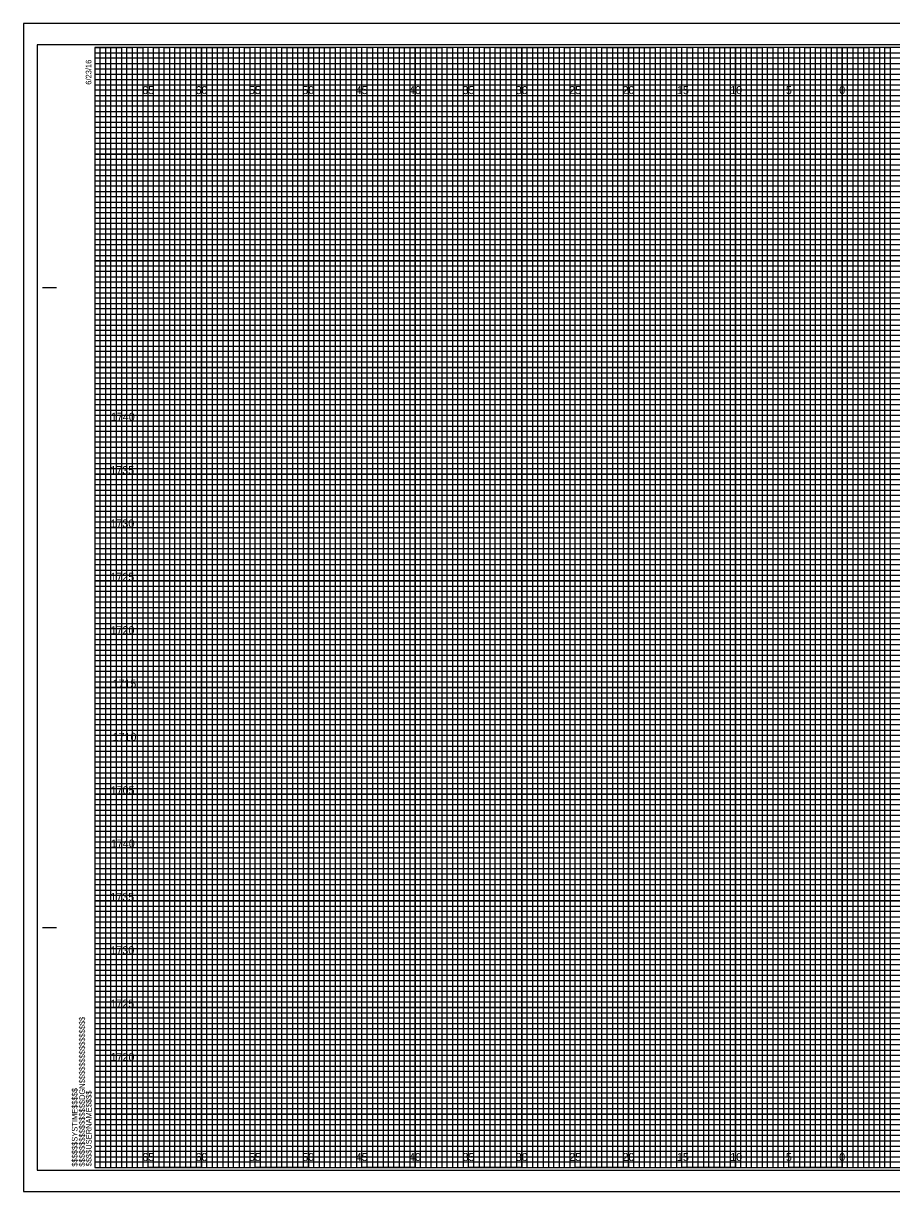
# Model space of a CAD drawing. Extents: x -7 to 162, y -2 to 217.
# Drawn here: x -6.7 to 74.6, y -2.3 to 107.3 of the extents above; entities that cross this region are included whole.
import ezdxf

# ---------------------------------------------------------------- set-up
doc = ezdxf.new("R2010")
doc.units = 0
for name, color, linetype in [('Prop XS Elevation Labels', 7, 'Continuous'), ('Prop XS Offset Labels', 7, 'Continuous'), ('Sheet Cross Section CELL', 7, 'Continuous'), ('Sheet Cross Section Grid Major CELL', 7, 'Continuous'), ('Sheet Cross Section Grid Middle CELL', 7, 'Continuous'), ('Sheet Cross Section Grid Minor 1 CELL', 7, 'Continuous'), ('Sheet Cross Section Grid Minor 2 CELL', 7, 'Continuous'), ('Sheet Cutting Line CELL', 7, 'Continuous'), ('Sheet DOT Grid CELL', 7, 'Continuous'), ('Sheet Plot Border Inside CELL', 7, 'Continuous'), ('Sheet Plot Border Outside CELL', 7, 'Continuous')]:
    doc.layers.add(name, color=color, linetype=linetype)

msp = doc.modelspace()

# ---------------------------------------------------------------- linework, layer by layer
at = {"layer": 'Sheet Cross Section CELL'}
for p, q in [((-4.9, 82.5), (-3.65, 82.5)), ((-4.85, 82.5), (-3.6, 82.5)), ((-4.9, 22.5), (-3.65, 22.5)), ((-4.85, 22.5), (-3.6, 22.5)), ((0, 0), (0, 0)), ((0, 0), (0, 0)), ((0, 0), (0, 0)), ((0, 0), (0, 0)), ((0, 0), (0, 0)), ((0, 0), (0, 0)), ((0, 0), (0, 0))]:
    msp.add_line(p, q, dxfattribs=at)
msp.add_lwpolyline([(160, 105), (0, 105), (0, 0), (160, 0)], close=True, dxfattribs=at)
at = {"layer": 'Sheet Cross Section Grid Major CELL'}
for p, q in [((5, 105), (0, 105)), ((5, 0), (5, 105)), ((15, 105), (10, 105)), ((10, 105), (10, 0)), ((15, 0), (15, 105)), ((25, 105), (20, 105)), ((20, 105), (20, 0)), ((25, 0), (25, 105)), ((35, 105), (30, 105)), ((30, 105), (30, 0)), ((35, 0), (35, 105)), ((45, 105), (40, 105)), ((40, 105), (40, 0)), ((45, 0), (45, 105)), ((55, 105), (50, 105)), ((50, 105), (50, 0)), ((55, 0), (55, 105)), ((65, 105), (60, 105)), ((60, 105), (60, 0)), ((65, 0), (65, 105)), ((75, 105), (70, 105)), ((70, 105), (70, 0)), ((10, 0), (5, 0)), ((20, 0), (15, 0)), ((30, 0), (25, 0)), ((40, 0), (35, 0)), ((50, 0), (45, 0)), ((60, 0), (55, 0)), ((70, 0), (65, 0))]:
    msp.add_line(p, q, dxfattribs=at)
for points in [[(0, 100), (160, 100), (160, 95), (0, 95)], [(0, 90), (160, 90), (160, 85), (0, 85)], [(0, 80), (160, 80), (160, 75), (0, 75)], [(0, 70), (160, 70), (160, 65), (0, 65)], [(0, 60), (160, 60), (160, 55), (0, 55)], [(0, 50), (160, 50), (160, 45), (0, 45)], [(0, 40), (160, 40), (160, 35), (0, 35)], [(0, 30), (160, 30), (160, 25), (0, 25)], [(0, 20), (160, 20), (160, 15), (0, 15)], [(0, 10), (160, 10), (160, 5), (0, 5)]]:
    msp.add_lwpolyline(points, dxfattribs=at)
at = {"layer": 'Sheet Cross Section Grid Middle CELL'}
for points in [[(0, 105), (2.5, 105), (2.5, 0), (7.5, 0), (7.5, 105), (12.5, 105), (12.5, 0), (17.5, 0), (17.5, 105), (22.5, 105), (22.5, 0), (27.5, 0), (27.5, 105), (32.5, 105), (32.5, 0), (37.5, 0), (37.5, 105), (42.5, 105), (42.5, 0), (47.5, 0), (47.5, 105), (52.5, 105), (52.5, 0), (57.5, 0), (57.5, 105), (62.5, 105), (62.5, 0), (67.5, 0), (67.5, 105), (72.5, 105), (72.5, 0), (77.5, 0)], [(0, 102.5), (137.5, 102.5)], [(0, 92.5), (160, 92.5), (160, 97.5), (0, 97.5)], [(0, 82.5), (160, 82.5), (160, 87.5), (0, 87.5)], [(0, 72.5), (160, 72.5), (160, 77.5), (0, 77.5)], [(0, 62.5), (160, 62.5), (160, 67.5), (0, 67.5)], [(0, 52.5), (160, 52.5), (160, 57.5), (0, 57.5)], [(0, 42.5), (160, 42.5), (160, 47.5), (0, 47.5)], [(0, 32.5), (160, 32.5), (160, 37.5), (0, 37.5)], [(0, 22.5), (160, 22.5), (160, 27.5), (0, 27.5)], [(0, 12.5), (160, 12.5), (160, 17.5), (0, 17.5)], [(0, 2.5), (160, 2.5), (160, 7.5), (0, 7.5)]]:
    msp.add_lwpolyline(points, dxfattribs=at)
at = {"layer": 'Sheet Cross Section Grid Minor 1 CELL'}
for p, q in [((0, 104.5), (130, 104.5)), ((130, 103.99), (0, 103.99)), ((0, 103.99), (0, 103.5)), ((0, 103.5), (130, 103.5)), ((130, 102.95), (0, 102.95)), ((0, 102.95), (0, 102)), ((0, 102), (160, 102))]:
    msp.add_line(p, q, dxfattribs=at)
for points in [[(0, 101.5), (135, 101.5), (160, 101.5), (160, 101), (0, 101)], [(0, 100.5), (160, 100.5), (160, 99.5), (0, 99.5)], [(0, 99), (160, 99), (160, 98.5), (0, 98.49)], [(0, 98), (160, 98), (160, 97), (0, 97)], [(0, 96.5), (160, 96.5), (160, 96), (0, 96)], [(0, 95.5), (160, 95.5), (160, 94.5), (0, 94.5)], [(0, 94), (160, 94), (160, 93.5), (0, 93.5)], [(0, 93), (160, 93), (160, 92), (0, 92)], [(0, 91.5), (160, 91.5), (160, 91), (0, 91)], [(0, 90.5), (160, 90.5), (160, 89.5), (0, 89.5)], [(0, 89), (160, 89), (160, 88.5), (0, 88.5)], [(0, 88), (160, 88), (160, 86.98), (160, 86.5), (160, 86), (0, 86)], [(0, 87), (160, 87), (160, 86.5), (0, 86.5)], [(0, 85.5), (160, 85.5), (160, 84.5), (0, 84.52)], [(0, 84.52), (160, 84.5), (160, 84), (0, 84)], [(0, 83.5), (160, 83.5), (160, 83), (0, 83)], [(0, 82), (160, 82), (160, 81.5), (0, 81.5)], [(0, 81), (160, 81), (160, 80.5), (0, 80.5)], [(-0.04, 79.45), (160, 79.45), (160, 78.94), (-0.04, 78.94)], [(0, 78.5), (160, 78.5), (160, 78), (0, 78)], [(0, 77), (160, 77), (160, 76.5), (0, 76.5)], [(0, 76), (160, 76), (160, 75.5), (0, 75.5)], [(0, 74.5), (160, 74.5), (160, 74), (0, 74)], [(0, 73.5), (160, 73.5), (160, 73), (0, 73)], [(0, 72), (160, 72), (160, 71.5), (0, 71.5)], [(0, 71), (160, 71), (160, 70.5), (0, 70.5)], [(0, 69.5), (160, 69.5), (160, 68.99), (0, 69)], [(0, 68.5), (160, 68.5), (160, 68), (0, 68)], [(0, 67), (160, 67), (160, 66.5), (0, 66.5)], [(0, 66), (160, 66), (160, 65.5), (0, 65.5)], [(0, 64.5), (160, 64.5), (160, 64), (0, 64)], [(0, 63.5), (160, 63.5), (160, 63), (0, 63)], [(0, 62), (160, 62), (160, 61.5), (0, 61.5)], [(0, 61), (160, 61), (160, 60.5), (0, 60.5)], [(0, 59.5), (160, 59.5), (160, 59), (0, 59)], [(0, 58.5), (160.03, 58.45), (160, 58), (0, 58)], [(0, 57), (160, 57), (160, 56.5), (0, 56.5)], [(0, 56), (160, 56), (160, 55.5), (0, 55.5)], [(0, 54.5), (160, 54.5), (160, 54), (0, 54)], [(0, 53.5), (160, 53.5), (160, 53), (0, 53)], [(0, 52), (160, 52), (160, 51.5), (0, 51.5)], [(0, 51), (160, 51), (160, 50.5), (0, 50.5)], [(0, 49.5), (160, 49.5), (160, 49), (0, 49)], [(0, 48.5), (160, 48.5), (160, 48), (0, 48)], [(0, 47), (160, 47), (160, 46.5), (0, 46.5)], [(0, 46), (160, 46), (160, 45.5), (0, 45.5)], [(0, 44.5), (160, 44.5), (160, 44), (0, 44)], [(0, 43.5), (160, 43.5), (160, 43), (0, 43)], [(0, 42), (160, 42), (160, 41.5), (0, 41.5)], [(0, 41), (160, 41), (160, 40.5), (0, 40.5)], [(0, 39.5), (160, 39.5), (160, 38.99), (0, 39)], [(0, 38.5), (160, 38.5), (160, 38), (0, 38)], [(0, 37), (160, 37), (160, 36.5), (0, 36.5)], [(0, 36), (160, 36), (160, 35.5), (0, 35.5)], [(0, 34.5), (160, 34.5), (160, 34), (0, 34)], [(0, 33.5), (160, 33.5), (160, 33), (0, 33)], [(0, 32), (160, 32), (160, 31.5), (0, 31.5)], [(0, 31), (160, 31), (160, 30.5), (0, 30.5)], [(0, 29.5), (160, 29.5), (160, 29), (0, 29)], [(0, 28.5), (160.03, 28.46), (160, 28), (0, 28)], [(0, 27), (160, 27), (160, 26.5), (0, 26.5)], [(0, 26), (160, 26), (160, 25.5), (0, 25.5)], [(0, 24.5), (160, 24.5), (160, 24), (0, 24)], [(0, 23.5), (160, 23.5), (160, 23), (0, 23)], [(0, 22), (160, 22), (160, 21.5), (0, 21.5)], [(0, 21), (160, 21), (160, 20.5), (0, 20.5)], [(0, 19.5), (160, 19.5), (160, 19), (0, 19)], [(0, 18.5), (160, 18.5), (160, 18), (0, 18)], [(0, 17), (160, 17), (160, 16.5), (0, 16.5)], [(0, 16), (160, 16), (160, 15.5), (0, 15.5)], [(0, 14.5), (160, 14.5), (160, 14), (0, 14)], [(0, 13.5), (160, 13.5), (160, 13), (0, 13)], [(0, 12), (160, 12), (160, 11.5), (0, 11.5)], [(0, 11), (160, 11), (160, 10.5), (0, 10.5)], [(0, 9.5), (160, 9.5), (160, 9), (0, 9)], [(0, 8.5), (160, 8.5), (160, 8), (0, 8)], [(0, 7), (160, 7), (160, 6.5), (0, 6.5)], [(0, 6), (160, 6), (160, 5.5), (0, 5.5)], [(0, 4.5), (160, 4.5), (160, 4), (0, 4)], [(0, 3.5), (160, 3.5), (160, 3), (0, 3)], [(0, 2), (160, 2), (160, 1.5), (0, 1.5)], [(0, 1), (160, 1), (160, 0.5), (0, 0.5)]]:
    msp.add_lwpolyline(points, dxfattribs=at)
at = {"layer": 'Sheet Cross Section Grid Minor 2 CELL'}
for points in [[(0, 0), (0.5, 0), (0.5, 105), (1, 105), (1, 0)], [(1, 0), (1.5, 0), (1.5, 105), (2, 105), (2, 0)], [(2.5, 0), (3, 0), (3, 105), (3.5, 105), (3.5, 0)], [(3.5, 0), (4, 0), (4, 105), (4.5, 105), (4.5, 0)], [(5, 0), (5.5, 0), (5.5, 105), (6, 105), (6, 0)], [(6, 0), (6.5, 0), (6.5, 105), (7, 105), (7, 0)], [(7.5, 0), (8, 0), (8, 105), (8.5, 105), (8.5, 0)], [(8.5, 0), (9, 0), (9, 105), (9.5, 105), (9.5, 0)], [(10, 0), (10.5, 0), (10.5, 105), (11, 105), (11, 0)], [(11, 0), (11.5, 0), (11.5, 105), (12, 105), (12, 0)], [(12.5, 0), (13, 0), (13, 105), (13.5, 105), (13.5, 0)], [(13.5, 0), (14, 0), (14, 105), (14.5, 105), (14.5, 0)], [(15, 0), (15.5, 0), (15.5, 105), (16, 105), (16, 0)], [(16, 0), (16.5, 0), (16.5, 105), (17, 105), (17, 0)], [(17.5, 0), (18, 0), (18, 105), (18.5, 105), (18.5, 0)], [(18.5, 0), (19, 0), (19, 105), (19.5, 105), (19.5, 0)], [(20, 0), (20.5, 0), (20.5, 105), (21, 105), (21, 0)], [(21, 0), (21.5, 0), (21.5, 105), (22, 105), (22, 0)], [(22.5, 0), (23, 0), (23, 105), (23.5, 105), (23.5, 0)], [(23.5, 0), (24, 0), (24, 105), (24.5, 105), (24.5, 0)], [(25, 0), (25.5, 0), (25.5, 105), (26, 105), (26, 0)], [(26, 0), (26.5, 0), (26.5, 105), (27, 105), (27, 0)], [(27.5, 0), (28, 0), (28, 105), (28.5, 105), (28.5, 0)], [(28.5, 0), (29, 0), (29, 105), (29.5, 105), (29.5, 0)], [(30, 0), (30.5, 0), (30.5, 105), (31, 105), (31, 0)], [(31, 0), (31.5, 0), (31.5, 105), (32, 105), (32, 0)], [(32.5, 0), (33, 0), (33, 105), (33.5, 105), (33.5, 0)], [(33.5, 0), (34, 0), (34, 105), (34.5, 105), (34.5, 0)], [(35, 0), (35.5, 0), (35.5, 105), (36, 105), (36, 0)], [(36, 0), (36.5, 0), (36.5, 105), (37, 105), (37, 0)], [(37.5, 0), (38, 0), (38, 105), (38.5, 105), (38.5, 0)], [(38.5, 0), (39, 0), (39, 105), (39.5, 105), (39.5, 0)], [(40, 0), (40.5, 0), (40.5, 105), (41, 105), (41, 0)], [(41, 0), (41.5, 0), (41.5, 105), (42, 105), (42, 0)], [(42.5, 0), (43, 0), (43, 105), (43.5, 105), (43.5, 0)], [(43.5, 0), (44, 0), (44, 105), (44.5, 105), (44.5, 0)], [(45, 0), (45.5, 0), (45.5, 105), (46, 105), (46, 0)], [(46, 0), (46.5, 0), (46.5, 105), (47, 105), (47, 0)], [(47.5, 0), (48, 0), (48, 105), (48.5, 105), (48.5, 0)], [(48.5, 0), (49, 0), (49, 105), (49.5, 105), (49.5, 0)], [(50, 0), (50.5, 0), (50.5, 105), (51, 105), (51, 0)], [(51, 0), (51.5, 0), (51.5, 105), (52, 105), (52, 0)], [(52.5, 0), (53, 0), (53, 105), (53.5, 105), (53.5, 0)], [(53.5, 0), (54, 0), (54, 105), (54.5, 105), (54.5, 0)], [(55, 0), (55.5, 0), (55.5, 105), (56, 105), (56, 0)], [(56, 0), (56.5, 0), (56.5, 105), (57, 105), (57, 0)], [(57.5, 0), (58, 0), (58, 105), (58.5, 105), (58.5, 0)], [(58.5, 0), (59, 0), (59, 105), (59.5, 105), (59.5, 0)], [(60, 0), (60.5, 0), (60.5, 105), (61, 105), (61, 0)], [(61, 0), (61.5, 0), (61.5, 105), (62, 105), (62, 0)], [(62.5, 0), (63, 0), (63, 105), (63.5, 105), (63.5, 0)], [(63.5, 0), (64, 0), (64, 105), (64.5, 105), (64.5, 0)], [(65, 0), (65.5, 0), (65.5, 105), (66, 105), (66, 0)], [(66, 0), (66.5, 0), (66.5, 105), (67, 105), (67, 0)], [(67.5, 0), (68, 0), (68, 105), (68.5, 105), (68.5, 0)], [(68.5, 0), (69, 0), (69, 105), (69.5, 105), (69.5, 0)], [(70, 0), (70.5, 0), (70.5, 105), (71, 105), (71, 0)], [(71, 0), (71.5, 0), (71.5, 105), (72, 105), (72, 0)], [(72.5, 0), (73, 0), (73, 105), (73.5, 105), (73.5, 0)], [(73.5, 0), (74, 0), (74, 105), (74.5, 105), (74.5, 0)]]:
    msp.add_lwpolyline(points, dxfattribs=at)
at = {"layer": 'Sheet Cutting Line CELL'}
for p, q in [((161.65, 107.25), (-6.7, 107.25)), ((-6.7, 107.25), (-6.7, -2.25)), ((-6.7, -2.25), (161.65, -2.25))]:
    msp.add_line(p, q, dxfattribs=at)
at = {"layer": 'Sheet DOT Grid CELL'}
for p, q in [((5, 0), (5, 105)), ((10, 0), (10, 105)), ((15, 0), (15, 105)), ((20, 0), (20, 105)), ((25, 0), (25, 105)), ((30, 0), (30, 105)), ((35, 0), (35, 105)), ((40, 0), (40, 105)), ((45, 0), (45, 105)), ((50, 0), (50, 105)), ((55, 0), (55, 105)), ((60, 0), (60, 105)), ((65, 0), (65, 105)), ((70, 0), (70, 105)), ((0, 100), (160, 100)), ((0, 95), (160, 95)), ((0, 90), (160, 90)), ((0, 85), (160, 85)), ((0, 80), (160, 80)), ((0, 75), (160, 75)), ((0, 70), (160, 70)), ((0, 65), (160, 65)), ((0, 60), (160, 60)), ((0, 55), (160, 55)), ((0, 50), (160, 50)), ((0, 45), (160, 45)), ((0, 40), (160, 40)), ((0, 35), (160, 35)), ((0, 30), (160, 30)), ((0, 25), (160, 25)), ((0, 20), (160, 20)), ((0, 15), (160, 15)), ((0, 10), (160, 10)), ((0, 5), (160, 5))]:
    msp.add_line(p, q, dxfattribs=at)
at = {"layer": 'Sheet Plot Border Inside CELL'}
msp.add_lwpolyline([(-5.4, -0.25), (161.2, -0.25), (161.2, 105.25), (-5.4, 105.25)], close=True, dxfattribs=at)
at = {"layer": 'Sheet Plot Border Outside CELL'}
msp.add_lwpolyline([(-6.7, -2.25), (161.65, -2.25), (161.65, 107.25), (-6.7, 107.25)], close=True, dxfattribs=at)

# ---------------------------------------------------------------- texts
at = {"layer": 'Prop XS Elevation Labels'}
for s, p in [('1740', (1.5, 70)), ('1735', (1.45, 65)), ('1730', (1.46, 60)), ('1725', (1.46, 55)), ('1720', (1.47, 50)), ('1715', (1.65, 45)), ('1710', (1.66, 40)), ('1705', (1.48, 35)), ('1740', (1.5, 30)), ('1735', (1.45, 25)), ('1730', (1.46, 20)), ('1725', (1.46, 15)), ('1720', (1.47, 10))]:
    msp.add_text(s, height=0.75, dxfattribs=at).set_placement(p)
at = {"layer": 'Prop XS Offset Labels'}
for s, p in [('65', (4.44, 100.62)), ('60', (9.43, 100.62)), ('55', (14.44, 100.62)), ('50', (19.43, 100.62)), ('45', (24.44, 100.62)), ('40', (29.43, 100.62)), ('35', (34.44, 100.62)), ('30', (39.43, 100.62)), ('25', (44.44, 100.62)), ('20', (49.43, 100.62)), ('15', (54.53, 100.62)), ('10', (59.52, 100.62)), ('5', (64.74, 100.62)), ('0', (69.73, 100.62)), ('0', (69.73, 100.62)), ('65', (4.44, 0.62)), ('60', (9.43, 0.62)), ('55', (14.44, 0.62)), ('50', (19.43, 0.62)), ('45', (24.44, 0.62)), ('40', (29.43, 0.62)), ('35', (34.44, 0.62)), ('30', (39.43, 0.62)), ('25', (44.44, 0.62)), ('20', (49.43, 0.62)), ('15', (54.53, 0.62)), ('10', (59.52, 0.62)), ('5', (64.74, 0.62)), ('0', (69.73, 0.62)), ('0', (69.73, 0.62))]:
    msp.add_text(s, height=0.75, dxfattribs=at).set_placement(p)
at = {"layer": 'Sheet Cross Section CELL'}
for s, p in [('6/23/16', (-0.33, 101.5)), ('$$$$$$$$$$$$$$$$DGN$$$$$$$$$$$$$$$$', (-0.94, 0.09)), ('$$$$$$SYSTIME$$$$$', (-1.63, 0.09)), ('$$$$USERNAME$$$$', (-0.31, 0.12))]:
    msp.add_text(s, height=0.525, rotation=90, dxfattribs=at).set_placement(p)

doc.saveas('drawing.dxf')
